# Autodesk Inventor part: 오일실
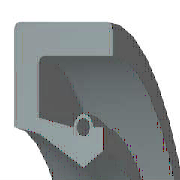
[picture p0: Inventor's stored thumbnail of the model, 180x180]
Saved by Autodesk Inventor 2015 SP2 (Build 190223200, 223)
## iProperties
IsCustomPart: 0
Created: 2009-02
Part Number: 오일실
Material: 고무
Description: 오일-실
Document SubType Name: Modeling
Standard: KS B 2804
Designer: 한국산업디자인학원 [http://gmhk.co.kr]
Standards Organization: KS
Language: ko-KR
Size Designation: S - 17 30 8
Categories: <MemberInstance><Categories><Category DisplayName="샤프트 부품" InternalName="7f7aeb1f-a693-4053-b835-cee3144e0d98" Mnemonic="SHFT"><Category DisplayName="실링" Intern
Density: 0.93 g/cm^3
Appearance: 고무 - 검은색 - 버전 1.1
Mass: 1.6913 g
Surface Area: 28.0102 cm^2
Volume: 1.81861 cm^3
Author: pww
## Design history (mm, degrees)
revolve "본체" stored, may be unused: angle "d17" = 90 deg
revolve "스프링1" stored, may be unused: angle "d18" = 90 deg
body "Solid1"
sketch "스케치1"
  geometry: L1 (0, 15)-(8, 15); L2 (8, 15)-(8, 13.75); L3 (8, 13.75)-(1.75, 13.75); L4 (0, 15)-(0, 10.6); L5 (0, 10.6)-(1.75, 10.25); L6 (1.75, 10.25)-(4.9, 8.5); L7 (4.9, 8.5)-(0, 8.5); L8 (6.3, 9.375)-(6.3, 10.6); L9 (0, 0)-(9.586, 0) reference; L10 (4.9, 8.5)-(6.3, 9.375); L11 (0, 18)-(0, -3) reference; L12 (-1.917, 0)-(11.503, 0) reference; L13 (4.2, 10.6)-(1.75, 11.09); L14 (1.75, 11.09)-(1.75, 13.75); L15 (6.3, 10.6)-(5.6, 10.6); C1 r 0.455 at (4.9, 10.6); A1 r 0.7 centre (4.9, 10.6) between (5.6, 10.6) and (4.2, 10.6)
  constraints: 26 end point, 5 horizontal alignment, 4 perpendicular, 2 centre point, 2 collinear, 2 horizontal, 2 parallel, 2 point on circle, 2 point on line, 2 vertical alignment, 1 coincident
  dimensions: "d0" = 30 diameter of L1 L9 (= SD2); "d1" = 18.75 diameter of L8.start L9 (= ABDM); "d2" = 1.25 distance of L1.end L2.end (computed from SD); "d3" = 0.91 diameter of C1 (= SPDI); "d4" = 1.4 diameter of A1 (= SPDA); "d5" = 17 diameter of L6.end L9 (= NND); "d6" = 20.5 diameter of L5.end L9 (= TKDM); "d7" = 21.2 diameter of L4.end L9 (= HLDM); "d8" = 4.9 distance from line of C1.centre L4 (= SPDST); "d9" = 6.3 distance between parallel lines of L8 L4 (= SDI); "d10" = 8 distance between parallel lines of L2 L4 (= SWDT); "d12" = 1.75 distance between parallel lines of L14 L4 (= SD)
fillet "모깎기1" dims "d11" = 0.3 (= RR)
other parameters: "SD2" = 30 [user parameter; used in 1 equation term], "SWDT" = 8 [user parameter; used in 1 equation term], "RR" = 0.3 [user parameter; used in 1 equation term], "SD" = 1.75 [user parameter; used in 2 equation terms], "NND" = 17 [user parameter; used in 1 equation term], "SPDA" = 1.4 [user parameter; used in 1 equation term], "SPDI" = 0.91 [user parameter; used in 1 equation term], "TKDM" = 20.5 [user parameter; used in 1 equation term], "HLDM" = 21.2 [user parameter; used in 1 equation term], "ABDM" = 18.75 [user parameter; used in 1 equation term], "SDI" = 6.3 [user parameter; used in 1 equation term], "SPDST" = 4.9 [user parameter; used in 1 equation term], "d13" = 0, "d14" = 0, "d15" = 0, "LAB" = 0.35 [user parameter]
